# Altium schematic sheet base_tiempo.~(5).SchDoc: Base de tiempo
size A4; Revision: 1
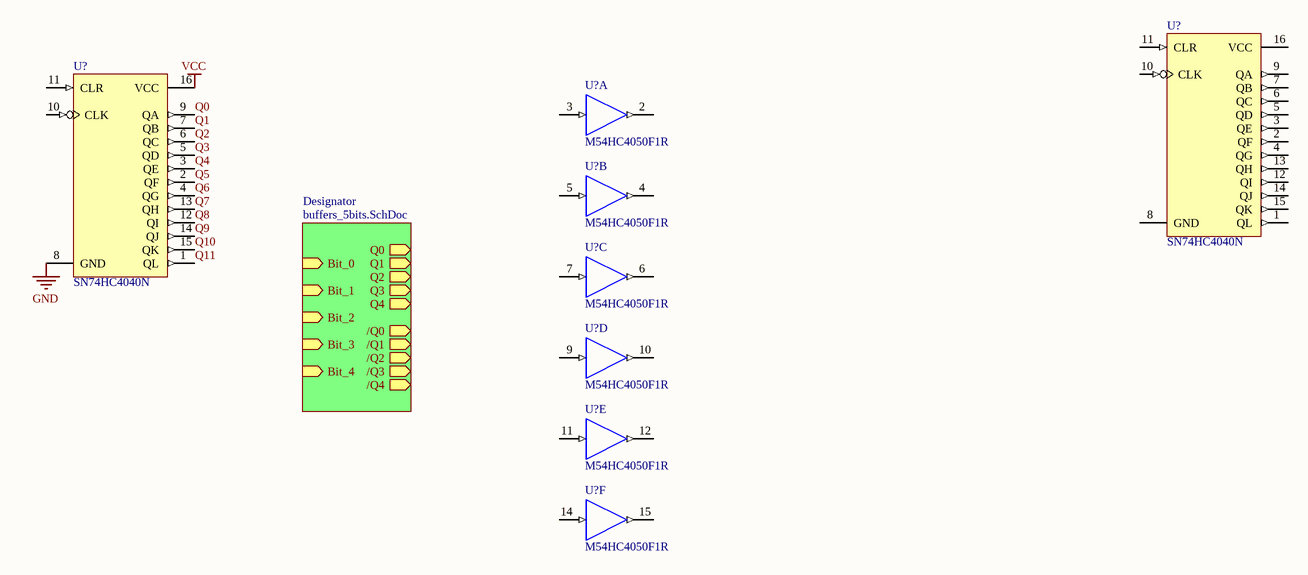
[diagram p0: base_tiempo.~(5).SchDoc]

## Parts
(Parts that share a designator on the sheet are numbered #1, #2 ... from top to bottom, then left to right.)
U?#1  SN74HC4040N  [N016]
U?#2  SN74HC4040N  [N016]
U?#3  M54HC4050F1R  [DIP16]  (part A of 6)
U?#4  M54HC4050F1R  [DIP16]  (part B of 6)
U?#5  M54HC4050F1R  [DIP16]  (part C of 6)
U?#6  M54HC4050F1R  [DIP16]  (part D of 6)
U?#7  M54HC4050F1R  [DIP16]  (part E of 6)
U?#8  M54HC4050F1R  [DIP16]  (part F of 6)

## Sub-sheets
Designator = buffers_5bits.SchDoc: Bit_0 (in), Bit_1 (in), Bit_2 (in), Bit_3 (in), Bit_4 (in), Q0 (out), Q1 (out), Q2 (out), Q3 (out), Q4 (out), /Q0 (out), /Q1 (out), /Q2 (out), /Q3 (out), /Q4 (out)

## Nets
GND: U?#2.8(GND) U?#3.8(GND) U?#4.8(GND) U?#5.8(GND) U?#6.8(GND) U?#7.8(GND) U?#8.8(GND)
VCC: U?#2.16(VCC) U?#3.1(VCC) U?#4.1(VCC) U?#5.1(VCC) U?#6.1(VCC) U?#7.1(VCC) U?#8.1(VCC)
Q0: U?#2.9(QA)
Q1: U?#2.7(QB)
Q2: U?#2.6(QC)
Q3: U?#2.5(QD)
Q4: U?#2.3(QE)
Q5: U?#2.2(QF)
Q6: U?#2.4(QG)
Q7: U?#2.13(QH)
Q8: U?#2.12(QI)
Q9: U?#2.14(QJ)
Q10: U?#2.15(QK)
Q11: U?#2.1(QL)

Not connected (* = marked no-connect by the designer): U?#1 1(QL) 2(QF) 3(QE) 4(QG) 5(QD) 6(QC) 7(QB) 8(GND) 9(QA) 10(CLK) 11(CLR) 12(QI) 13(QH) 14(QJ) 15(QK) 16(VCC); U?#2 10(CLK) 11(CLR); U?#3 2(Y) 3(A); U?#4 4(Y) 5(A); U?#5 6(Y) 7(A); U?#6 9(A) 10(Y); U?#7 11(A) 12(Y); U?#8 14(A) 15(Y)

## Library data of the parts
U?#1 U?#2 = SN74HC4040N: 12-Bit Asynchronous Binary Counter
U?#3-U?#8 = M54HC4050F1R: Hex Buffer/Converter Non-Inverting; Note: Pins 13 and 16 are not connected and not drawn.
